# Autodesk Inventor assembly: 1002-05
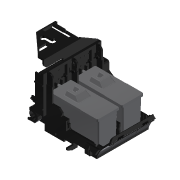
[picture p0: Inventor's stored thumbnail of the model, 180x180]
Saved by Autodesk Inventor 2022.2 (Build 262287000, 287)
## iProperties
Company: Autodesk Inc.
Created: 2006-02
Part Number: 1002-05
Document SubType Name: Assembly
Designer: Autodesk Inc.
Mass: 103.338 g
Surface Area: 1093.7 cm^2
Volume: 88.6869 cm^3
Density: 1.1652 g/cm^3
Description: CARTRIDGE ASSEMBLY
Author: Inventor
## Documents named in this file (4)
- D:\Inventor\Tutorial 2\第1回 AnyCAD\Workspaces\Workspace\Cartridge Assembly.iam
- D:\Inventor\Tutorial 2\第1回 AnyCAD\Workspaces\Workspace\cartridge seat.ipt
- D:\Inventor\Tutorial 2\第1回 AnyCAD\Workspaces\Workspace\Cartridge Panel.ipt
- D:\Inventor\Tutorial 2\第1回 AnyCAD\Workspaces\Workspace\Ink Cartridge.ipt
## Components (4 placed, 3 different names)
1. cartridge seat:1 — Mate:1, Mate:3, Mate:4, Mate:9, Mate:10, Mate:11, Mate:12, Flush:4
2. Cartridge Long Life:1 — Mate:1, Flush:1, Mate:12
3. Cartridge Long Life:2 — Mate:3, Mate:4, Flush:1
4. cartridge seat panel:1 — Mate:9, Mate:10, Mate:11
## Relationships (9: Mate 7, Flush 2)
- Mate:1: cartridge seat:1 ↔ Cartridge Long Life:1
- Mate:3: cartridge seat:1 ↔ Cartridge Long Life:2
- Mate:4: cartridge seat:1 ↔ Cartridge Long Life:2
- Flush:1: Cartridge Long Life:1 ↔ Cartridge Long Life:2
- Mate:9: cartridge seat:1 ↔ cartridge seat panel:1
- Mate:10: cartridge seat:1 ↔ cartridge seat panel:1
- Mate:11: cartridge seat:1 ↔ cartridge seat panel:1
- Mate:12: cartridge seat:1 ↔ Cartridge Long Life:1
- Flush:4: cartridge seat:1
